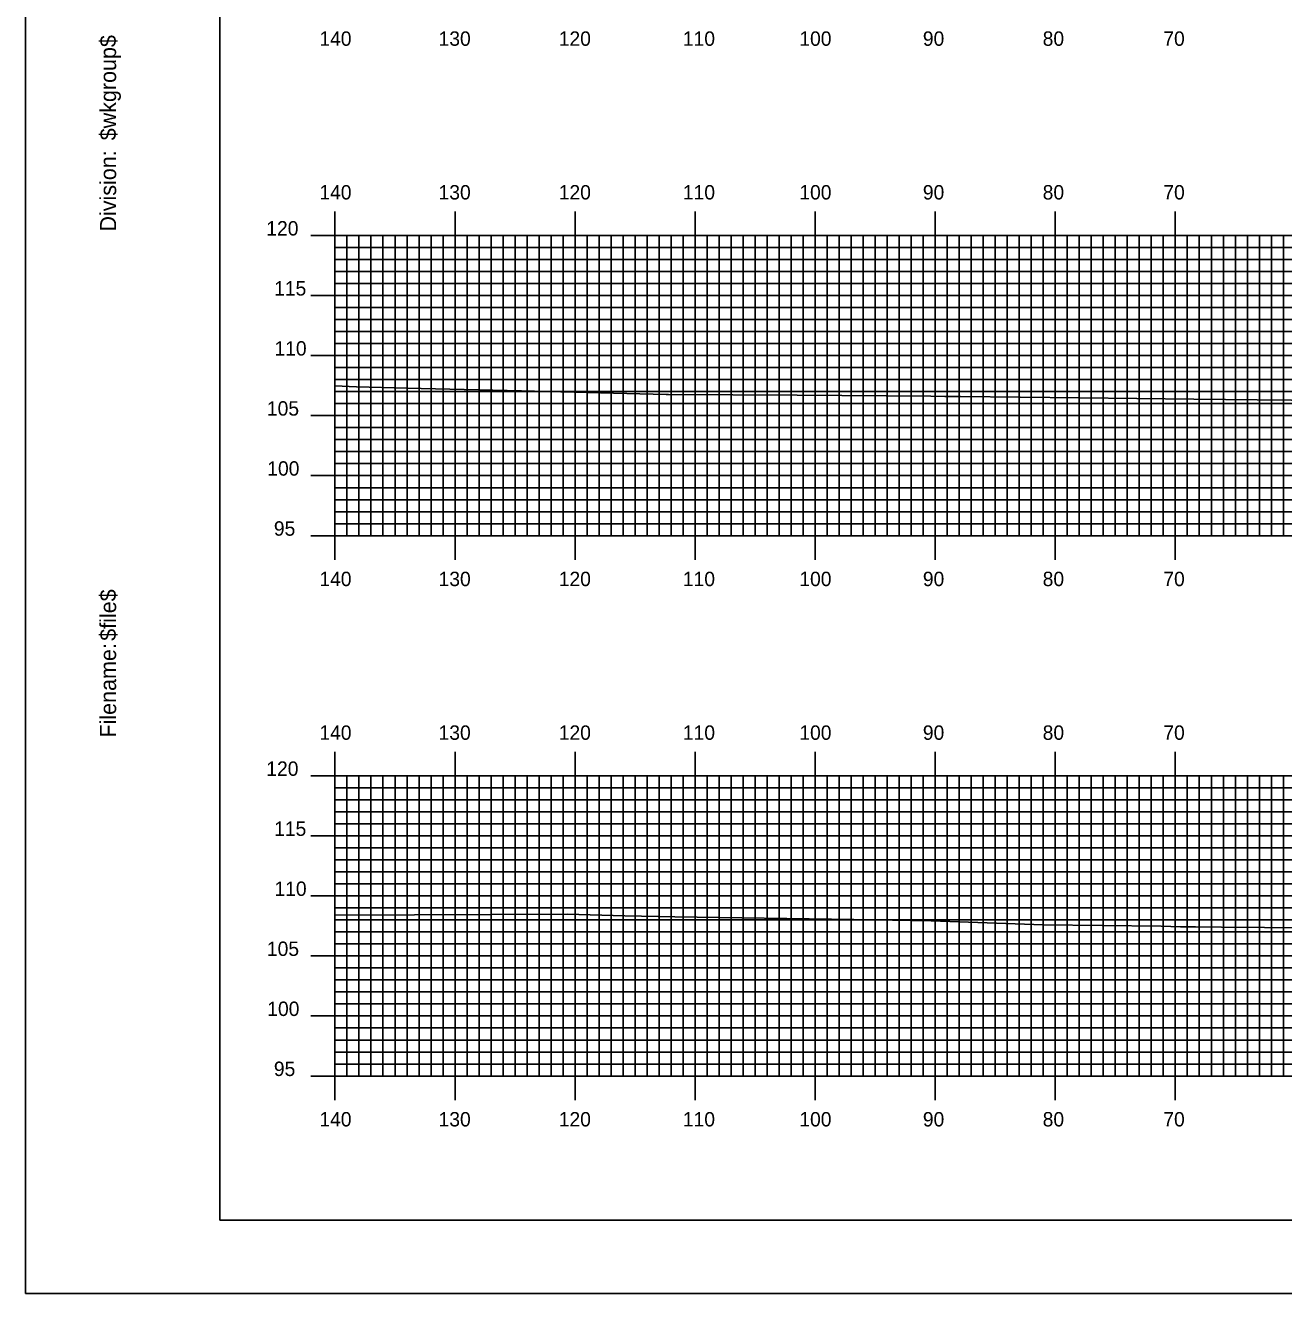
# Model space of a CAD drawing. Extents: x 1773596 to 1773940, y 442591 to 442811.
# Drawn here: x 1773596.4 to 1773701.2, y 442590.5 to 442696.2 of the extents above; entities that cross this region are included whole.
import ezdxf

# ---------------------------------------------------------------- set-up
doc = ezdxf.new("R2010")
doc.units = 0
for name, color, linetype in [('BORDER', 7, 'Continuous'), ('H_V ANNOTATION', 7, 'Continuous'), ('MAJOR', 7, 'Continuous'), ('MINOR', 7, 'Continuous'), ('PLOT BOUNDARY', 7, 'Continuous'), ('S_Roadway_Centerline', 7, 'Continuous')]:
    doc.layers.add(name, color=color, linetype=linetype)

msp = doc.modelspace()

# ---------------------------------------------------------------- linework, layer by layer
at = {"layer": 'BORDER'}
msp.add_lwpolyline([(1773612.55, 442596.67), (1773932.55, 442596.67), (1773932.55, 442806.67), (1773612.55, 442806.67)], close=True, dxfattribs=at)
at = {"layer": 'MAJOR'}
for p, q in [((1773622.15, 442680.67), (1773622.15, 442678.67)), ((1773632.15, 442680.67), (1773632.15, 442678.67)), ((1773642.15, 442680.67), (1773642.15, 442678.67)), ((1773652.15, 442680.67), (1773652.15, 442678.67)), ((1773662.15, 442680.67), (1773662.15, 442678.67)), ((1773672.15, 442680.67), (1773672.15, 442678.67)), ((1773682.15, 442680.67), (1773682.15, 442678.67)), ((1773692.15, 442680.67), (1773692.15, 442678.67)), ((1773620.14, 442678.67), (1773622.15, 442678.67)), ((1773622.15, 442678.67), (1773902.15, 442678.67)), ((1773622.15, 442653.67), (1773622.15, 442678.67)), ((1773622.15, 442653.67), (1773622.15, 442678.67)), ((1773622.15, 442678.67), (1773902.15, 442678.67)), ((1773632.15, 442653.67), (1773632.15, 442678.67)), ((1773642.15, 442653.67), (1773642.15, 442678.67)), ((1773652.15, 442653.67), (1773652.15, 442678.67)), ((1773662.15, 442653.67), (1773662.15, 442678.67)), ((1773672.15, 442653.67), (1773672.15, 442678.67)), ((1773682.15, 442653.67), (1773682.15, 442678.67)), ((1773692.15, 442653.67), (1773692.15, 442678.67)), ((1773620.14, 442673.67), (1773622.15, 442673.67)), ((1773622.15, 442673.67), (1773902.15, 442673.67)), ((1773620.14, 442668.67), (1773622.15, 442668.67)), ((1773622.15, 442668.67), (1773902.15, 442668.67)), ((1773620.14, 442663.67), (1773622.15, 442663.67)), ((1773622.15, 442663.67), (1773902.15, 442663.67)), ((1773620.14, 442658.67), (1773622.15, 442658.67)), ((1773622.15, 442658.67), (1773902.15, 442658.67)), ((1773620.14, 442653.67), (1773622.15, 442653.67)), ((1773622.15, 442653.67), (1773902.15, 442653.67)), ((1773622.15, 442653.67), (1773902.15, 442653.67)), ((1773622.15, 442651.66), (1773622.15, 442653.67)), ((1773632.15, 442651.66), (1773632.15, 442653.67)), ((1773642.15, 442651.66), (1773642.15, 442653.67)), ((1773652.15, 442651.66), (1773652.15, 442653.67)), ((1773662.15, 442651.66), (1773662.15, 442653.67)), ((1773672.15, 442651.66), (1773672.15, 442653.67)), ((1773682.15, 442651.66), (1773682.15, 442653.67)), ((1773692.15, 442651.66), (1773692.15, 442653.67)), ((1773622.15, 442635.67), (1773622.15, 442633.67)), ((1773632.15, 442635.67), (1773632.15, 442633.67)), ((1773642.15, 442635.67), (1773642.15, 442633.67)), ((1773652.15, 442635.67), (1773652.15, 442633.67)), ((1773662.15, 442635.67), (1773662.15, 442633.67)), ((1773672.15, 442635.67), (1773672.15, 442633.67)), ((1773682.15, 442635.67), (1773682.15, 442633.67)), ((1773692.15, 442635.67), (1773692.15, 442633.67)), ((1773620.14, 442633.67), (1773622.15, 442633.67)), ((1773622.15, 442633.67), (1773902.15, 442633.67)), ((1773622.15, 442608.67), (1773622.15, 442633.67)), ((1773622.15, 442608.67), (1773622.15, 442633.67)), ((1773622.15, 442633.67), (1773902.15, 442633.67)), ((1773632.15, 442608.67), (1773632.15, 442633.67)), ((1773642.15, 442608.67), (1773642.15, 442633.67)), ((1773652.15, 442608.67), (1773652.15, 442633.67)), ((1773662.15, 442608.67), (1773662.15, 442633.67)), ((1773672.15, 442608.67), (1773672.15, 442633.67)), ((1773682.15, 442608.67), (1773682.15, 442633.67)), ((1773692.15, 442608.67), (1773692.15, 442633.67)), ((1773620.14, 442628.67), (1773622.15, 442628.67)), ((1773622.15, 442628.67), (1773902.15, 442628.67)), ((1773620.14, 442623.67), (1773622.15, 442623.67)), ((1773622.15, 442623.67), (1773902.15, 442623.67)), ((1773620.14, 442618.67), (1773622.15, 442618.67)), ((1773622.15, 442618.67), (1773902.15, 442618.67)), ((1773620.14, 442613.67), (1773622.15, 442613.67)), ((1773622.15, 442613.67), (1773902.15, 442613.67)), ((1773620.14, 442608.67), (1773622.15, 442608.67)), ((1773622.15, 442608.67), (1773902.15, 442608.67)), ((1773622.15, 442608.67), (1773902.15, 442608.67)), ((1773622.15, 442606.66), (1773622.15, 442608.67)), ((1773632.15, 442606.66), (1773632.15, 442608.67)), ((1773642.15, 442606.66), (1773642.15, 442608.67)), ((1773652.15, 442606.66), (1773652.15, 442608.67)), ((1773662.15, 442606.66), (1773662.15, 442608.67)), ((1773672.15, 442606.66), (1773672.15, 442608.67)), ((1773682.15, 442606.66), (1773682.15, 442608.67)), ((1773692.15, 442606.66), (1773692.15, 442608.67))]:
    msp.add_line(p, q, dxfattribs=at)
at = {"layer": 'MINOR'}
for p, q in [((1773623.15, 442653.67), (1773623.15, 442678.67)), ((1773624.15, 442653.67), (1773624.15, 442678.67)), ((1773625.15, 442653.67), (1773625.15, 442678.67)), ((1773626.15, 442653.67), (1773626.15, 442678.67)), ((1773627.15, 442653.67), (1773627.15, 442678.67)), ((1773628.15, 442653.67), (1773628.15, 442678.67)), ((1773629.15, 442653.67), (1773629.15, 442678.67)), ((1773630.15, 442653.67), (1773630.15, 442678.67)), ((1773631.15, 442653.67), (1773631.15, 442678.67)), ((1773633.15, 442653.67), (1773633.15, 442678.67)), ((1773634.15, 442653.67), (1773634.15, 442678.67)), ((1773635.15, 442653.67), (1773635.15, 442678.67)), ((1773636.15, 442653.67), (1773636.15, 442678.67)), ((1773637.15, 442653.67), (1773637.15, 442678.67)), ((1773638.15, 442653.67), (1773638.15, 442678.67)), ((1773639.15, 442653.67), (1773639.15, 442678.67)), ((1773640.15, 442653.67), (1773640.15, 442678.67)), ((1773641.15, 442653.67), (1773641.15, 442678.67)), ((1773643.15, 442653.67), (1773643.15, 442678.67)), ((1773644.15, 442653.67), (1773644.15, 442678.67)), ((1773645.15, 442653.67), (1773645.15, 442678.67)), ((1773646.15, 442653.67), (1773646.15, 442678.67)), ((1773647.15, 442653.67), (1773647.15, 442678.67)), ((1773648.15, 442653.67), (1773648.15, 442678.67)), ((1773649.15, 442653.67), (1773649.15, 442678.67)), ((1773650.15, 442653.67), (1773650.15, 442678.67)), ((1773651.15, 442653.67), (1773651.15, 442678.67)), ((1773653.15, 442653.67), (1773653.15, 442678.67)), ((1773654.15, 442653.67), (1773654.15, 442678.67)), ((1773655.15, 442653.67), (1773655.15, 442678.67)), ((1773656.15, 442653.67), (1773656.15, 442678.67)), ((1773657.15, 442653.67), (1773657.15, 442678.67)), ((1773658.15, 442653.67), (1773658.15, 442678.67)), ((1773659.15, 442653.67), (1773659.15, 442678.67)), ((1773660.15, 442653.67), (1773660.15, 442678.67)), ((1773661.15, 442653.67), (1773661.15, 442678.67)), ((1773663.15, 442653.67), (1773663.15, 442678.67)), ((1773664.15, 442653.67), (1773664.15, 442678.67)), ((1773665.15, 442653.67), (1773665.15, 442678.67)), ((1773666.15, 442653.67), (1773666.15, 442678.67)), ((1773667.15, 442653.67), (1773667.15, 442678.67)), ((1773668.15, 442653.67), (1773668.15, 442678.67)), ((1773669.15, 442653.67), (1773669.15, 442678.67)), ((1773670.15, 442653.67), (1773670.15, 442678.67)), ((1773671.15, 442653.67), (1773671.15, 442678.67)), ((1773673.15, 442653.67), (1773673.15, 442678.67)), ((1773674.15, 442653.67), (1773674.15, 442678.67)), ((1773675.15, 442653.67), (1773675.15, 442678.67)), ((1773676.15, 442653.67), (1773676.15, 442678.67)), ((1773677.15, 442653.67), (1773677.15, 442678.67)), ((1773678.15, 442653.67), (1773678.15, 442678.67)), ((1773679.15, 442653.67), (1773679.15, 442678.67)), ((1773680.15, 442653.67), (1773680.15, 442678.67)), ((1773681.15, 442653.67), (1773681.15, 442678.67)), ((1773683.15, 442653.67), (1773683.15, 442678.67)), ((1773684.15, 442653.67), (1773684.15, 442678.67)), ((1773685.15, 442653.67), (1773685.15, 442678.67)), ((1773686.15, 442653.67), (1773686.15, 442678.67)), ((1773687.15, 442653.67), (1773687.15, 442678.67)), ((1773688.15, 442653.67), (1773688.15, 442678.67)), ((1773689.15, 442653.67), (1773689.15, 442678.67)), ((1773690.15, 442653.67), (1773690.15, 442678.67)), ((1773691.15, 442653.67), (1773691.15, 442678.67)), ((1773693.15, 442653.67), (1773693.15, 442678.67)), ((1773694.15, 442653.67), (1773694.15, 442678.67)), ((1773695.15, 442653.67), (1773695.15, 442678.67)), ((1773696.15, 442653.67), (1773696.15, 442678.67)), ((1773697.15, 442653.67), (1773697.15, 442678.67)), ((1773698.15, 442653.67), (1773698.15, 442678.67)), ((1773699.15, 442653.67), (1773699.15, 442678.67)), ((1773700.15, 442653.67), (1773700.15, 442678.67)), ((1773701.15, 442653.67), (1773701.15, 442678.67)), ((1773622.15, 442677.67), (1773902.15, 442677.67)), ((1773622.15, 442677.67), (1773624.15, 442677.67)), ((1773622.15, 442676.67), (1773902.15, 442676.67)), ((1773622.15, 442676.67), (1773624.15, 442676.67)), ((1773622.15, 442675.67), (1773902.15, 442675.67)), ((1773622.15, 442675.67), (1773624.15, 442675.67)), ((1773622.15, 442674.67), (1773902.15, 442674.67)), ((1773622.15, 442674.67), (1773624.15, 442674.67)), ((1773622.15, 442672.67), (1773902.15, 442672.67)), ((1773622.15, 442672.67), (1773624.15, 442672.67)), ((1773622.15, 442671.67), (1773902.15, 442671.67)), ((1773622.15, 442671.67), (1773624.15, 442671.67)), ((1773622.15, 442670.67), (1773902.15, 442670.67)), ((1773622.15, 442670.67), (1773624.15, 442670.67)), ((1773622.15, 442669.67), (1773902.15, 442669.67)), ((1773622.15, 442669.67), (1773624.15, 442669.67)), ((1773622.15, 442667.67), (1773902.15, 442667.67)), ((1773622.15, 442667.67), (1773624.15, 442667.67)), ((1773622.15, 442666.67), (1773902.15, 442666.67)), ((1773622.15, 442666.67), (1773624.15, 442666.67)), ((1773622.15, 442665.67), (1773902.15, 442665.67)), ((1773622.15, 442665.67), (1773624.15, 442665.67)), ((1773622.15, 442664.67), (1773902.15, 442664.67)), ((1773622.15, 442664.67), (1773624.15, 442664.67)), ((1773622.15, 442662.67), (1773902.15, 442662.67)), ((1773622.15, 442662.67), (1773624.15, 442662.67)), ((1773622.15, 442661.67), (1773902.15, 442661.67)), ((1773622.15, 442661.67), (1773624.15, 442661.67)), ((1773622.15, 442660.67), (1773902.15, 442660.67)), ((1773622.15, 442660.67), (1773624.15, 442660.67)), ((1773622.15, 442659.67), (1773902.15, 442659.67)), ((1773622.15, 442659.67), (1773624.15, 442659.67)), ((1773622.15, 442657.67), (1773902.15, 442657.67)), ((1773622.15, 442657.67), (1773624.15, 442657.67)), ((1773622.15, 442656.67), (1773902.15, 442656.67)), ((1773622.15, 442656.67), (1773624.15, 442656.67)), ((1773622.15, 442655.67), (1773902.15, 442655.67)), ((1773622.15, 442655.67), (1773624.15, 442655.67)), ((1773622.15, 442654.67), (1773902.15, 442654.67)), ((1773622.15, 442654.67), (1773624.15, 442654.67)), ((1773623.15, 442608.67), (1773623.15, 442633.67)), ((1773624.15, 442608.67), (1773624.15, 442633.67)), ((1773625.15, 442608.67), (1773625.15, 442633.67)), ((1773626.15, 442608.67), (1773626.15, 442633.67)), ((1773627.15, 442608.67), (1773627.15, 442633.67)), ((1773628.15, 442608.67), (1773628.15, 442633.67)), ((1773629.15, 442608.67), (1773629.15, 442633.67)), ((1773630.15, 442608.67), (1773630.15, 442633.67)), ((1773631.15, 442608.67), (1773631.15, 442633.67)), ((1773633.15, 442608.67), (1773633.15, 442633.67)), ((1773634.15, 442608.67), (1773634.15, 442633.67)), ((1773635.15, 442608.67), (1773635.15, 442633.67)), ((1773636.15, 442608.67), (1773636.15, 442633.67)), ((1773637.15, 442608.67), (1773637.15, 442633.67)), ((1773638.15, 442608.67), (1773638.15, 442633.67)), ((1773639.15, 442608.67), (1773639.15, 442633.67)), ((1773640.15, 442608.67), (1773640.15, 442633.67)), ((1773641.15, 442608.67), (1773641.15, 442633.67)), ((1773643.15, 442608.67), (1773643.15, 442633.67)), ((1773644.15, 442608.67), (1773644.15, 442633.67)), ((1773645.15, 442608.67), (1773645.15, 442633.67)), ((1773646.15, 442608.67), (1773646.15, 442633.67)), ((1773647.15, 442608.67), (1773647.15, 442633.67)), ((1773648.15, 442608.67), (1773648.15, 442633.67)), ((1773649.15, 442608.67), (1773649.15, 442633.67)), ((1773650.15, 442608.67), (1773650.15, 442633.67)), ((1773651.15, 442608.67), (1773651.15, 442633.67)), ((1773653.15, 442608.67), (1773653.15, 442633.67)), ((1773654.15, 442608.67), (1773654.15, 442633.67)), ((1773655.15, 442608.67), (1773655.15, 442633.67)), ((1773656.15, 442608.67), (1773656.15, 442633.67)), ((1773657.15, 442608.67), (1773657.15, 442633.67)), ((1773658.15, 442608.67), (1773658.15, 442633.67)), ((1773659.15, 442608.67), (1773659.15, 442633.67)), ((1773660.15, 442608.67), (1773660.15, 442633.67)), ((1773661.15, 442608.67), (1773661.15, 442633.67)), ((1773663.15, 442608.67), (1773663.15, 442633.67)), ((1773664.15, 442608.67), (1773664.15, 442633.67)), ((1773665.15, 442608.67), (1773665.15, 442633.67)), ((1773666.15, 442608.67), (1773666.15, 442633.67)), ((1773667.15, 442608.67), (1773667.15, 442633.67)), ((1773668.15, 442608.67), (1773668.15, 442633.67)), ((1773669.15, 442608.67), (1773669.15, 442633.67)), ((1773670.15, 442608.67), (1773670.15, 442633.67)), ((1773671.15, 442608.67), (1773671.15, 442633.67)), ((1773673.15, 442608.67), (1773673.15, 442633.67)), ((1773674.15, 442608.67), (1773674.15, 442633.67)), ((1773675.15, 442608.67), (1773675.15, 442633.67)), ((1773676.15, 442608.67), (1773676.15, 442633.67)), ((1773677.15, 442608.67), (1773677.15, 442633.67)), ((1773678.15, 442608.67), (1773678.15, 442633.67)), ((1773679.15, 442608.67), (1773679.15, 442633.67)), ((1773680.15, 442608.67), (1773680.15, 442633.67)), ((1773681.15, 442608.67), (1773681.15, 442633.67)), ((1773683.15, 442608.67), (1773683.15, 442633.67)), ((1773684.15, 442608.67), (1773684.15, 442633.67)), ((1773685.15, 442608.67), (1773685.15, 442633.67)), ((1773686.15, 442608.67), (1773686.15, 442633.67)), ((1773687.15, 442608.67), (1773687.15, 442633.67)), ((1773688.15, 442608.67), (1773688.15, 442633.67)), ((1773689.15, 442608.67), (1773689.15, 442633.67)), ((1773690.15, 442608.67), (1773690.15, 442633.67)), ((1773691.15, 442608.67), (1773691.15, 442633.67)), ((1773693.15, 442608.67), (1773693.15, 442633.67)), ((1773694.15, 442608.67), (1773694.15, 442633.67)), ((1773695.15, 442608.67), (1773695.15, 442633.67)), ((1773696.15, 442608.67), (1773696.15, 442633.67)), ((1773697.15, 442608.67), (1773697.15, 442633.67)), ((1773698.15, 442608.67), (1773698.15, 442633.67)), ((1773699.15, 442608.67), (1773699.15, 442633.67)), ((1773700.15, 442608.67), (1773700.15, 442633.67)), ((1773701.15, 442608.67), (1773701.15, 442633.67)), ((1773622.15, 442632.67), (1773902.15, 442632.67)), ((1773622.15, 442632.67), (1773624.15, 442632.67)), ((1773622.15, 442631.67), (1773902.15, 442631.67)), ((1773622.15, 442631.67), (1773624.15, 442631.67)), ((1773622.15, 442630.67), (1773902.15, 442630.67)), ((1773622.15, 442630.67), (1773624.15, 442630.67)), ((1773622.15, 442629.67), (1773902.15, 442629.67)), ((1773622.15, 442629.67), (1773624.15, 442629.67)), ((1773622.15, 442627.67), (1773902.15, 442627.67)), ((1773622.15, 442627.67), (1773624.15, 442627.67)), ((1773622.15, 442626.67), (1773902.15, 442626.67)), ((1773622.15, 442626.67), (1773624.15, 442626.67)), ((1773622.15, 442625.67), (1773902.15, 442625.67)), ((1773622.15, 442625.67), (1773624.15, 442625.67)), ((1773622.15, 442624.67), (1773902.15, 442624.67)), ((1773622.15, 442624.67), (1773624.15, 442624.67)), ((1773622.15, 442622.67), (1773902.15, 442622.67)), ((1773622.15, 442622.67), (1773624.15, 442622.67)), ((1773622.15, 442621.67), (1773902.15, 442621.67)), ((1773622.15, 442621.67), (1773624.15, 442621.67)), ((1773622.15, 442620.67), (1773902.15, 442620.67)), ((1773622.15, 442620.67), (1773624.15, 442620.67)), ((1773622.15, 442619.67), (1773902.15, 442619.67)), ((1773622.15, 442619.67), (1773624.15, 442619.67)), ((1773622.15, 442617.67), (1773902.15, 442617.67)), ((1773622.15, 442617.67), (1773624.15, 442617.67)), ((1773622.15, 442616.67), (1773902.15, 442616.67)), ((1773622.15, 442616.67), (1773624.15, 442616.67)), ((1773622.15, 442615.67), (1773902.15, 442615.67)), ((1773622.15, 442615.67), (1773624.15, 442615.67)), ((1773622.15, 442614.67), (1773902.15, 442614.67)), ((1773622.15, 442614.67), (1773624.15, 442614.67)), ((1773622.15, 442612.67), (1773902.15, 442612.67)), ((1773622.15, 442612.67), (1773624.15, 442612.67)), ((1773622.15, 442611.67), (1773902.15, 442611.67)), ((1773622.15, 442611.67), (1773624.15, 442611.67)), ((1773622.15, 442610.67), (1773902.15, 442610.67)), ((1773622.15, 442610.67), (1773624.15, 442610.67)), ((1773622.15, 442609.67), (1773902.15, 442609.67)), ((1773622.15, 442609.67), (1773624.15, 442609.67))]:
    msp.add_line(p, q, dxfattribs=at)
at = {"layer": 'PLOT BOUNDARY'}
msp.add_lwpolyline([(1773596.36, 442590.55), (1773936.36, 442590.55), (1773936.36, 442810.55), (1773596.36, 442810.55)], close=True, dxfattribs=at)
at = {"layer": 'S_Roadway_Centerline'}
for points in [[(1773622.15, 442666.14), (1773623.95, 442666.08), (1773628.14, 442665.97), (1773637.68, 442665.74), (1773649.73, 442665.43), (1773649.83, 442665.42), (1773649.94, 442665.42), (1773660.64, 442665.37), (1773671.79, 442665.29), (1773672.95, 442665.27), (1773674.25, 442665.27), (1773684.19, 442665.14), (1773693.7, 442665.03), (1773698.97, 442664.99), (1773707.58, 442664.91)], [(1773622.15, 442622.07), (1773628.78, 442622.1), (1773641.49, 442622.14), (1773646.29, 442622.02), (1773650.45, 442621.94), (1773665.38, 442621.7), (1773671.81, 442621.6), (1773681.15, 442621.27), (1773690.98, 442621.16), (1773692.57, 442621.1), (1773693.82, 442621.1), (1773696.01, 442621.08), (1773728.32, 442620.83), (1773736.55, 442620.25), (1773740.9, 442620.02), (1773750.8, 442619.96), (1773758.76, 442619.59), (1773762.04, 442619.52), (1773765.97, 442619.57), (1773778.91, 442619.6), (1773789.34, 442619.39), (1773796.7, 442619.37), (1773802.63, 442619.28), (1773812.5, 442619.22)]]:
    msp.add_lwpolyline(points, dxfattribs=at)

# ---------------------------------------------------------------- texts
at = {"layer": 'BORDER'}
for s, p in [('$wkgroup$', (1773603.92, 442686.6)), ('Division:', (1773603.92, 442679)), ('$file$', (1773603.92, 442644.92)), ('Filename:', (1773603.92, 442636.86))]:
    msp.add_text(s, height=1.339, rotation=90, dxfattribs=at).set_placement(p)
at = {"layer": 'H_V ANNOTATION'}
for s, p in [('140', (1773620.85, 442694.47)), ('130', (1773630.78, 442694.47)), ('120', (1773640.79, 442694.47)), ('110', (1773651.13, 442694.47)), ('100', (1773660.83, 442694.47)), ('90', (1773671.12, 442694.47)), ('80', (1773681.1, 442694.47)), ('70', (1773691.15, 442694.47)), ('140', (1773620.85, 442681.67)), ('130', (1773630.78, 442681.67)), ('120', (1773640.79, 442681.67)), ('110', (1773651.13, 442681.67)), ('100', (1773660.83, 442681.67)), ('90', (1773671.12, 442681.67)), ('80', (1773681.1, 442681.67)), ('70', (1773691.15, 442681.67)), ('120', (1773616.43, 442678.67)), ('115', (1773617.08, 442673.67)), ('110', (1773617.11, 442668.67)), ('105', (1773616.48, 442663.67)), ('100', (1773616.51, 442658.67)), ('95', (1773617.06, 442653.67)), ('140', (1773620.85, 442649.47)), ('130', (1773630.78, 442649.47)), ('120', (1773640.79, 442649.47)), ('110', (1773651.13, 442649.47)), ('100', (1773660.83, 442649.47)), ('90', (1773671.12, 442649.47)), ('80', (1773681.1, 442649.47)), ('70', (1773691.15, 442649.47)), ('140', (1773620.85, 442636.67)), ('130', (1773630.78, 442636.67)), ('120', (1773640.79, 442636.67)), ('110', (1773651.13, 442636.67)), ('100', (1773660.83, 442636.67)), ('90', (1773671.12, 442636.67)), ('80', (1773681.1, 442636.67)), ('70', (1773691.15, 442636.67)), ('120', (1773616.43, 442633.67)), ('115', (1773617.08, 442628.67)), ('110', (1773617.11, 442623.67)), ('105', (1773616.48, 442618.67)), ('100', (1773616.51, 442613.67)), ('95', (1773617.06, 442608.67)), ('140', (1773620.85, 442604.47)), ('130', (1773630.78, 442604.47)), ('120', (1773640.79, 442604.47)), ('110', (1773651.13, 442604.47)), ('100', (1773660.83, 442604.47)), ('90', (1773671.12, 442604.47)), ('80', (1773681.1, 442604.47)), ('70', (1773691.15, 442604.47))]:
    msp.add_text(s, height=1.2, dxfattribs=at).set_placement(p)
at = {"layer": 'MAJOR'}
for p in [(1773622.14, 442653.67), (1773622.14, 442608.67)]:
    msp.add_text('-', height=0.012, dxfattribs=at).set_placement(p)

doc.saveas('drawing.dxf')
